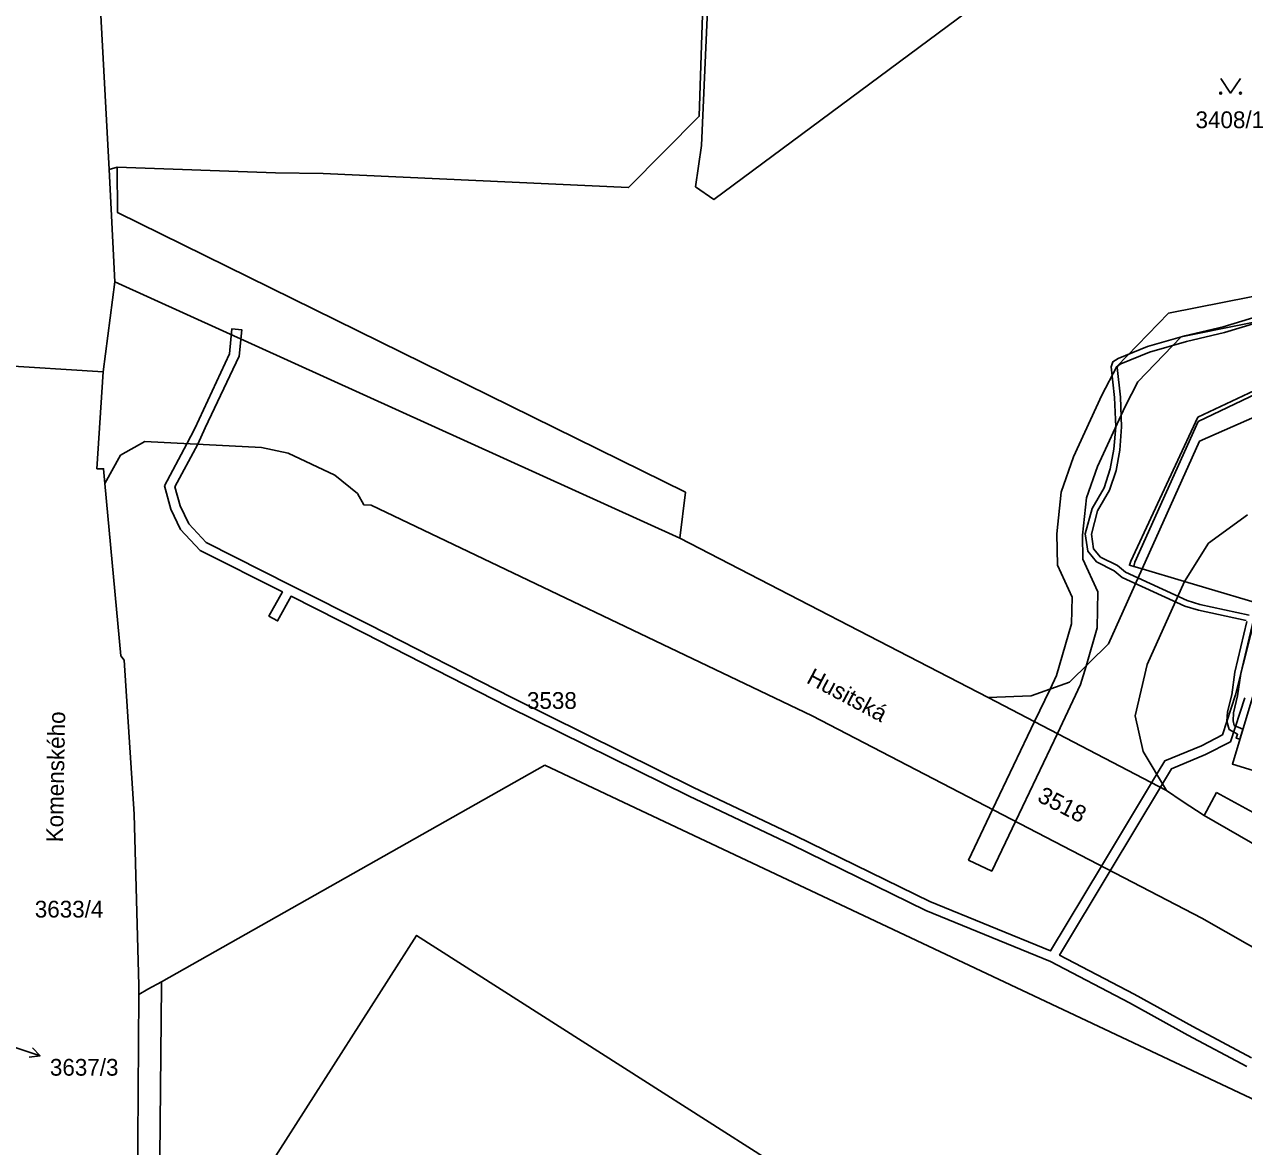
# Model space of a CAD drawing. Extents: x -869103 to -863415, y -1015889 to -1012477.
# Drawn here: x -867343.5 to -867219.9, y -1014312 to -1014198.2 of the extents above; entities that cross this region are included whole.
import ezdxf

# ---------------------------------------------------------------- set-up
doc = ezdxf.new("R2010")
doc.units = 0
for name, color, linetype in [('Hranice parcel', 7, 'Continuous'), ('Parcelní čísla', 7, 'Continuous'), ('Pop  PČ popisy', 7, 'Continuous'), ('Vnitřní kresba', 7, 'Continuous'), ('Věcná břemena k části', 7, 'Continuous'), ('Značky kultur', 7, 'Continuous')]:
    doc.layers.add(name, color=color, linetype=linetype)

msp = doc.modelspace()

# ---------------------------------------------------------------- linework, layer by layer
at = {"layer": 'Hranice parcel'}
for p, q in [((-867340.19, -1014116.8), (-867334.88, -1014212.9)), ((-867334.88, -1014212.9), (-867334.08, -1014212.67)), ((-867334.3, -1014224.27), (-867334.88, -1014212.9)), ((-867335.51, -1014233.4), (-867334.3, -1014224.27)), ((-867224.5, -1014238), (-867207.32, -1014229.91)), ((-867346.25, -1014232.75), (-867335.51, -1014233.4)), ((-867329.6, -1014295.27), (-867290.73, -1014273.3)), ((-867224.11, -1014288.83), (-867206.26, -1014298.99)), ((-867331.87, -1014295.65), (-867331.87, -1014296.55)), ((-867331.97, -1014311.36), (-867331.87, -1014296.55))]:
    msp.add_line(p, q, dxfattribs=at)
for points in [[(-867272.93, -1014167.67), (-867274.83, -1014210.45), (-867275.44, -1014214.65), (-867273.58, -1014215.92), (-867168.75, -1014138.16)], [(-867334.08, -1014212.67), (-867318.01, -1014213.22), (-867313.2, -1014213.29), (-867282.22, -1014214.73), (-867275.06, -1014207.5), (-867274.24, -1014182.76), (-867273.81, -1014167.11)], [(-867334.08, -1014212.67), (-867334.03, -1014217.27), (-867276.46, -1014245.63), (-867277.04, -1014250.29), (-867245.76, -1014266.43)], [(-867335.51, -1014233.4), (-867336.14, -1014243.24), (-867335.45, -1014243.24), (-867335.33, -1014244.75)], [(-867216.31, -1014257.51), (-867225.86, -1014254.68), (-867230.16, -1014253.41), (-867231, -1014253.16), (-867231.44, -1014253.03), (-867231.31, -1014252.6), (-867224.5, -1014238)], [(-867335.33, -1014244.75), (-867333.75, -1014241.87), (-867331.28, -1014240.48), (-867319.46, -1014241.1), (-867316.73, -1014241.66), (-867312.02, -1014243.9), (-867309.72, -1014245.75), (-867309.07, -1014246.9), (-867308.33, -1014246.95), (-867263.6, -1014268.3), (-867224.11, -1014288.83)], [(-867335.33, -1014244.75), (-867333.72, -1014262.21), (-867333.36, -1014262.66), (-867332.34, -1014278.26), (-867331.87, -1014295.65)], [(-867216.31, -1014257.51), (-867221, -1014273.2), (-867213.49, -1014275.51), (-867209.33, -1014276.78)], [(-867245.76, -1014266.43), (-867227.69, -1014275.87), (-867226.08, -1014276.97)], [(-867290.73, -1014273.3), (-867283.35, -1014276.78), (-867213.18, -1014309.9)], [(-867226.08, -1014276.97), (-867223.88, -1014278.42), (-867178.16, -1014304.73)], [(-867294.18, -1014330.25), (-867280.02, -1014339.42), (-867277.16, -1014341.27), (-867262.67, -1014318.45), (-867261.92, -1014317.27), (-867280.69, -1014305.28), (-867303.72, -1014290.57), (-867317.75, -1014312.56), (-867318.84, -1014314.28), (-867316.17, -1014316.01), (-867295.58, -1014329.35)], [(-867331.87, -1014296.55), (-867330.96, -1014296.03), (-867329.6, -1014295.27)], [(-867329.75, -1014313.05), (-867329.6, -1014295.64), (-867329.6, -1014295.27)], [(-867334.14, -1014344.33), (-867332.78, -1014328.2), (-867332.25, -1014318.78), (-867332.03, -1014318.78), (-867331.97, -1014311.36)]]:
    msp.add_lwpolyline(points, dxfattribs=at)
at = {"layer": 'Pop  PČ popisy'}
for p, q in [((-867344.74, -1014301.84), (-867341.89, -1014302.77)), ((-867341.89, -1014302.77), (-867342.68, -1014301.98)), ((-867341.89, -1014302.77), (-867342.99, -1014302.93))]:
    msp.add_line(p, q, dxfattribs=at)
at = {"layer": 'Vnitřní kresba'}
for p, q in [((-867334.3, -1014224.27), (-867277.04, -1014250.29)), ((-867224.47, -1014238.45), (-867207.44, -1014230.31)), ((-867224.33, -1014240.45), (-867208.4, -1014233.43)), ((-867230.88, -1014252.73), (-867224.47, -1014238.45)), ((-867230.16, -1014253.41), (-867224.33, -1014240.45)), ((-867223.43, -1014250.79), (-867219.48, -1014247.93)), ((-867223.43, -1014250.79), (-867225.86, -1014254.68)), ((-867231, -1014253.16), (-867230.88, -1014252.73)), ((-867230.16, -1014253.41), (-867233.58, -1014261.01)), ((-867229.65, -1014263.1), (-867225.86, -1014254.68)), ((-867233.58, -1014261.01), (-867237.52, -1014264.9)), ((-867230.87, -1014268.31), (-867229.65, -1014263.1)), ((-867237.52, -1014264.9), (-867241.39, -1014266.27)), ((-867241.39, -1014266.27), (-867245.76, -1014266.43)), ((-867230.05, -1014271.93), (-867230.87, -1014268.31)), ((-867227.69, -1014275.87), (-867230.05, -1014271.93)), ((-867223.88, -1014278.42), (-867222.6, -1014276.08)), ((-867222.6, -1014276.08), (-867185.57, -1014296.39))]:
    msp.add_line(p, q, dxfattribs=at)
at = {"layer": 'Věcná břemena k části'}
for points in [[(-867213.63, -1014224.71), (-867227.48, -1014227.47), (-867232.71, -1014232.89), (-867234.23, -1014235.78), (-867237.1, -1014242.04), (-867238.35, -1014245.61), (-867238.79, -1014249.86), (-867238.75, -1014253.01), (-867237.26, -1014256.28), (-867237.33, -1014258.97), (-867238.83, -1014264.22), (-867239.49, -1014265.6), (-867241.06, -1014268.89), (-867245.31, -1014277.81), (-867247.75, -1014282.93), (-867245.41, -1014284.05), (-867243, -1014279.01), (-867238.75, -1014270.09), (-867236.39, -1014265.14), (-867235.84, -1014263.25), (-867234.73, -1014259.37), (-867234.64, -1014255.74), (-867236.15, -1014252.43), (-867236.19, -1014249.98), (-867235.79, -1014246.19), (-867234.68, -1014243.02), (-867231.89, -1014236.92), (-867230.59, -1014234.43), (-867226.18, -1014229.87), (-867213.41, -1014227.31)], [(-867213.58, -1014226.3), (-867221.95, -1014228.85), (-867225.82, -1014229.76), (-867229.6, -1014230.83), (-867232.6, -1014232.07), (-867233.12, -1014232.4), (-867233.29, -1014232.9), (-867232.96, -1014236.02), (-867232.83, -1014238.98), (-867233.01, -1014241.27), (-867233.38, -1014243.26), (-867234.02, -1014245.17), (-867235.23, -1014247.27), (-867235.92, -1014249.84), (-867235.65, -1014251.61), (-867234.78, -1014252.68), (-867233, -1014253.59), (-867232.17, -1014254.26), (-867225.82, -1014257.17), (-867224.45, -1014257.6), (-867219.61, -1014258.65)], [(-867219.29, -1014258.09), (-867224.29, -1014257.02), (-867225.6, -1014256.61), (-867231.85, -1014253.74), (-867232.66, -1014253.07), (-867234.38, -1014252.2), (-867235.07, -1014251.35), (-867235.3, -1014249.88), (-867234.67, -1014247.51), (-867233.46, -1014245.43), (-867232.78, -1014243.42), (-867232.41, -1014241.35), (-867232.23, -1014239), (-867232.36, -1014235.98), (-867232.67, -1014232.96), (-867232.62, -1014232.8), (-867232.32, -1014232.61), (-867229.4, -1014231.41), (-867225.66, -1014230.34), (-867221.79, -1014229.43), (-867213.52, -1014226.92)], [(-867218.39, -1014257.09), (-867220.7, -1014266.19), (-867222.02, -1014270.23), (-867224.15, -1014271.34), (-867227.86, -1014272.88), (-867229.19, -1014275.09), (-867234.27, -1014283.55), (-867239.43, -1014292.14), (-867251.67, -1014287.12), (-867265.3, -1014280.46), (-867275.64, -1014275.56), (-867294, -1014266.49), (-867308.56, -1014259.03), (-867316.42, -1014255.07), (-867325.06, -1014250.71), (-867326.81, -1014248.83), (-867327.7, -1014246.99), (-867328.22, -1014245.08), (-867325.91, -1014240.76), (-867325.14, -1014239.08), (-867321.71, -1014231.84), (-867321.45, -1014229.14), (-867322.45, -1014229.04), (-867322.69, -1014231.58), (-867326.2, -1014239.17), (-867327.02, -1014240.7), (-867329.28, -1014244.96), (-867328.64, -1014247.34), (-867327.65, -1014249.4), (-867325.67, -1014251.53), (-867317.33, -1014255.73), (-867318.69, -1014258.19), (-867317.81, -1014258.67), (-867316.44, -1014256.18), (-867309.02, -1014259.93), (-867294.45, -1014267.39), (-867276.08, -1014276.46), (-867265.74, -1014281.36), (-867252.08, -1014288.04), (-867239.45, -1014293.21), (-867231.44, -1014297.41), (-867225.51, -1014300.7), (-867219.55, -1014303.87)], [(-867219.53, -1014258.73), (-867220.76, -1014263.89), (-867221.07, -1014266.17), (-867221.49, -1014267.89), (-867221.55, -1014268.86), (-867221.34, -1014269.68), (-867220.47, -1014270.17), (-867220.61, -1014270.57), (-867220.25, -1014270.68), (-867219.94, -1014269.64), (-867220.82, -1014269.28), (-867220.93, -1014268.8), (-867220.89, -1014267.99), (-867220.47, -1014266.29), (-867220.16, -1014264.01), (-867218.87, -1014258.55)], [(-867219.05, -1014302.99), (-867225.03, -1014299.82), (-867230.96, -1014296.53), (-867238.52, -1014292.57), (-867233.38, -1014284.01), (-867228.3, -1014275.55), (-867227.18, -1014273.68), (-867223.73, -1014272.24), (-867221.2, -1014270.93), (-867219.74, -1014266.47)]]:
    msp.add_lwpolyline(points, dxfattribs=at)
at = {"layer": 'Značky kultur'}
msp.add_lwpolyline([(-867222.19, -1014203.65), (-867221.19, -1014205.15), (-867220.19, -1014203.65)], dxfattribs=at)
for centre in [(-867222.19, -1014205.15), (-867220.19, -1014205.15)]:
    msp.add_circle(centre, 0.1, dxfattribs=at)

# ---------------------------------------------------------------- texts
at = {"layer": 'Parcelní čísla'}
for s, p in [('3408/1', (-867224.74, -1014208.7)), ('3538', (-867292.53, -1014267.6)), ('3633/4', (-867342.43, -1014288.76)), ('3637/3', (-867340.9, -1014304.8))]:
    msp.add_text(s, height=1.7, dxfattribs=at).set_placement(p)
msp.add_text('3518', height=1.7, rotation=333, dxfattribs=at).set_placement((-867240.89, -1014276.92))
at = {"layer": 'Pop  PČ popisy'}
for s, rotation, p in [('Husitská', 332, (-867264.29, -1014264.9)), ('Komenského', 89, (-867339.58, -1014281.14))]:
    msp.add_text(s, height=1.7, rotation=rotation, dxfattribs=at).set_placement(p)

doc.saveas('drawing.dxf')
